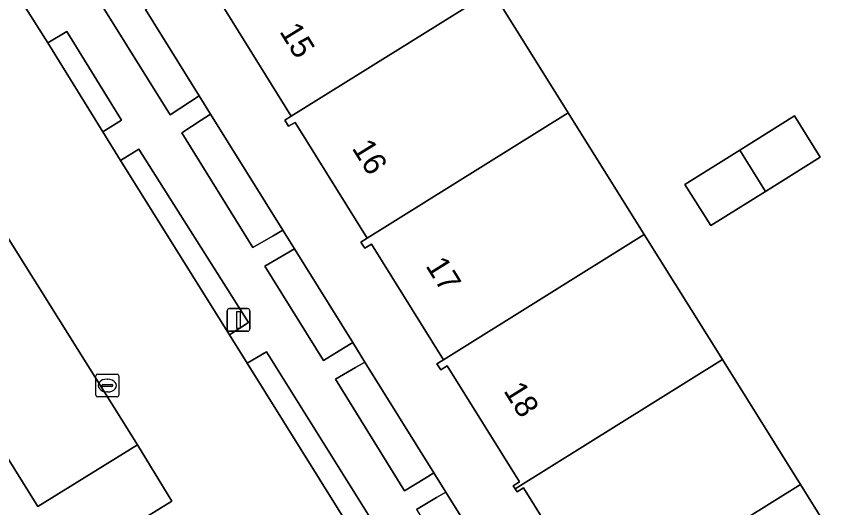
# Model space of a CAD drawing. Extents: x 159279 to 160377, y 384531 to 385888.
# Drawn here: x 159510.12 to 159545.75, y 385322.46 to 385344.02 of the extents above; entities that cross this region are included whole.
import ezdxf

# ---------------------------------------------------------------- set-up
doc = ezdxf.new("R2010")
doc.units = 0
for name, color, linetype in [('IMGEO_Erf', 7, 'Continuous'), ('IMGEO_Groenvoorziening', 7, 'Continuous'), ('IMGEO_Kolk', 7, 'Continuous'), ('IMGEO_Lichtmast', 7, 'Continuous'), ('IMGEO_Pand', 7, 'Continuous'), ('IMGEO_Pand_nummerreeks', 7, 'Continuous'), ('IMGEO_Parkeervlak_open', 7, 'Continuous'), ('IMGEO_Rijbaan_lokaal_open', 7, 'Continuous'), ('IMGEO_Terreindeel_gesloten', 7, 'Continuous'), ('IMGEO_Voetpad_open', 7, 'Continuous')]:
    doc.layers.add(name, color=color, linetype=linetype)

msp = doc.modelspace()

# ---------------------------------------------------------------- linework, layer by layer
at = {"layer": 'IMGEO_Erf'}
msp.add_lwpolyline([(159545.911, 385362.141), (159544.219, 385361.084), (159526.589, 385350.077), (159526.643, 385349.992), (159527.598, 385350.585), (159530.751, 385345.531), (159530.995, 385345.14), (159534.332, 385339.79), (159537.665, 385334.447), (159541.091, 385328.956), (159544.511, 385323.473), (159547.84, 385318.137)], dxfattribs=at)
msp.add_lwpolyline([(159540.589, 385334.838), (159539.447, 385336.633), (159541.856, 385338.146), (159544.259, 385339.654), (159545.385, 385337.84), (159542.987, 385336.339)], close=True, dxfattribs=at)
at = {"layer": 'IMGEO_Groenvoorziening'}
for points in [[(159500.64, 385348.943), (159498.146, 385352.954), (159493.776, 385350.243), (159488.31, 385359.005), (159492.658, 385361.728), (159490.152, 385365.746), (159485.794, 385363.031), (159480.341, 385371.812), (159484.701, 385374.506), (159481.423, 385379.772), (159481.223, 385380.079), (159473.614, 385375.297), (159509.752, 385318.295), (159516.946, 385322.749), (159515.441, 385325.224), (159511.063, 385322.514), (159504.254, 385333.446), (159508.6, 385336.129), (159506.114, 385340.158), (159501.739, 385337.466), (159496.29, 385346.227)], [(159526.567, 385349.945), (159526.643, 385349.992), (159526.589, 385350.077), (159525.637, 385351.642), (159513.967, 385344.361), (159516.864, 385339.703), (159517.725, 385340.259), (159518.148, 385340.532), (159516.872, 385342.583), (159515.793, 385344.318), (159516.58, 385344.813), (159519.338, 385346.547), (159519.862, 385345.731)], [(159511.503, 385342.85), (159513.916, 385338.953), (159514.742, 385339.457), (159512.339, 385343.356)], [(159518.645, 385339.732), (159518.225, 385339.457), (159517.377, 385338.902), (159520.499, 385333.876), (159521.386, 385334.392), (159521.813, 385334.64)], [(159514.691, 385337.689), (159519.469, 385330.043), (159520.3, 385330.582), (159515.497, 385338.189)], [(159522.321, 385333.823), (159521.898, 385333.572), (159521.021, 385333.05), (159523.596, 385328.915), (159524.466, 385329.457), (159524.878, 385329.713)], [(159520.255, 385328.8), (159525.749, 385319.979), (159526.576, 385320.524), (159521.094, 385329.298)], [(159525.415, 385328.849), (159524.997, 385328.606), (159524.117, 385328.095), (159527.153, 385323.192), (159528.035, 385323.738), (159528.439, 385323.988)], [(159528.965, 385323.142), (159528.556, 385322.903), (159527.669, 385322.385), (159530.249, 385318.277), (159531.106, 385318.817), (159531.501, 385319.066)]]:
    msp.add_lwpolyline(points, close=True, dxfattribs=at)
at = {"layer": 'IMGEO_Kolk'}
for p, q in [((159513.689, 385328.32), (159514.541, 385328.32)), ((159513.614, 385327.394), (159513.614, 385328.246)), ((159514.102, 385328.1), (159514.127, 385328.1)), ((159514.615, 385328.246), (159514.615, 385327.394)), ((159513.873, 385327.814), (159513.873, 385327.826)), ((159514.311, 385327.777), (159513.913, 385327.777)), ((159513.916, 385327.863), (159514.314, 385327.863)), ((159514.357, 385327.826), (159514.357, 385327.814)), ((159514.541, 385327.32), (159513.689, 385327.32)), ((159514.125, 385327.54), (159514.1, 385327.54))]:
    msp.add_line(p, q, dxfattribs=at)
for points in [[(159513.689, 385328.32), (159514.541, 385328.32)], [(159513.614, 385327.394), (159513.614, 385328.246)], [(159514.615, 385328.246), (159514.615, 385327.394)], [(159514.541, 385327.32), (159513.689, 385327.32)]]:
    msp.add_lwpolyline(points, dxfattribs=at)
for centre, radius, start, end in [((159513.691, 385328.244), 0.0765, 91.552, 178.448), ((159513.691, 385328.244), 0.0765, 91.552, 178.448), ((159514.539, 385328.244), 0.0765, 1.552, 88.448), ((159514.539, 385328.244), 0.0765, 1.552, 88.448), ((159513.913, 385327.823), 0.0403, 85.8775, 175.7526), ((159513.91, 385327.813), 0.0366, 178.938, 274.7102), ((159514.314, 385327.82), 0.043, 264.8664, 352.4533), ((159514.318, 385327.825), 0.0386, 1.7309, 96.639), ((159513.691, 385327.396), 0.0765, 181.552, 268.448), ((159513.691, 385327.396), 0.0765, 181.552, 268.448), ((159514.539, 385327.396), 0.0765, 271.552, 358.448), ((159514.539, 385327.396), 0.0765, 271.552, 358.448)]:
    msp.add_arc(centre, radius, start, end, dxfattribs=at)
for centre, major_axis, ratio, start_param, end_param in [((159514.101, 385327.82), (-0.387, 0.002), 0.722429, 4.712389, 7.853982), ((159514.126, 385327.82), (-0.39, 0.002), 0.717154, 1.570796, 4.712389)]:
    msp.add_ellipse(centre, major_axis=major_axis, ratio=ratio, start_param=start_param, end_param=end_param, dxfattribs=at)
at = {"layer": 'IMGEO_Lichtmast'}
for p, q in [((159519.472, 385331.198), (159520.262, 385331.198)), ((159520.262, 385331.198), (159519.472, 385331.198)), ((159519.372, 385330.298), (159519.372, 385331.098)), ((159519.372, 385331.098), (159519.372, 385330.298)), ((159520.362, 385331.098), (159520.362, 385330.298)), ((159520.362, 385330.298), (159520.362, 385331.098)), ((159520.262, 385330.198), (159519.472, 385330.198)), ((159519.472, 385330.198), (159520.262, 385330.198))]:
    msp.add_line(p, q, dxfattribs=at)
msp.add_lwpolyline([(159519.792, 385331.073), (159519.942, 385331.073), (159519.942, 385330.323), (159519.792, 385330.323), (159519.792, 385331.073)], dxfattribs=at)
for centre, start, end in [((159519.472, 385331.098), 90, 180), ((159519.472, 385331.098), 90, 180), ((159520.262, 385331.098), 0, 90), ((159520.262, 385331.098), 360, 90), ((159519.472, 385330.298), 180, 270), ((159519.472, 385330.298), 180, 270), ((159520.262, 385330.298), 270, 0), ((159520.262, 385330.298), 270, 0)]:
    msp.add_arc(centre, 0.1, start, end, dxfattribs=at)
at = {"layer": 'IMGEO_Pand'}
for points in [[(159527.598, 385350.585), (159526.643, 385349.992), (159526.567, 385349.945), (159519.862, 385345.731), (159518.525, 385344.89), (159518.698, 385344.614), (159518.995, 385344.793), (159522.171, 385339.635), (159530.995, 385345.14), (159530.751, 385345.531)], [(159534.332, 385339.79), (159530.995, 385345.14), (159522.171, 385339.635), (159521.895, 385339.464), (159522.061, 385339.196), (159522.355, 385339.363), (159525.505, 385334.283)], [(159537.665, 385334.447), (159534.332, 385339.79), (159525.505, 385334.283), (159525.23, 385334.113), (159525.413, 385333.844), (159525.695, 385334.022), (159528.852, 385328.949)], [(159541.856, 385338.146), (159542.987, 385336.339), (159545.385, 385337.84), (159544.259, 385339.654)], [(159542.987, 385336.339), (159541.856, 385338.146), (159539.447, 385336.633), (159540.589, 385334.838)], [(159541.091, 385328.956), (159537.665, 385334.447), (159528.852, 385328.949), (159528.57, 385328.77), (159528.748, 385328.501), (159529.026, 385328.677), (159532.188, 385323.601), (159531.909, 385323.415), (159531.997, 385323.284)], [(159544.511, 385323.473), (159541.091, 385328.956), (159531.997, 385323.284), (159532.084, 385323.155), (159532.372, 385323.337), (159535.532, 385318.259), (159535.244, 385318.069), (159535.419, 385317.802), (159535.707, 385317.981)], [(159547.84, 385318.137), (159544.511, 385323.473), (159535.707, 385317.981), (159538.867, 385312.913), (159538.572, 385312.73), (159538.749, 385312.469), (159539.017, 385312.633)]]:
    msp.add_lwpolyline(points, close=True, dxfattribs=at)
at = {"layer": 'IMGEO_Parkeervlak_open'}
msp.add_lwpolyline([(159508.6, 385336.129), (159504.254, 385333.446), (159511.063, 385322.514), (159515.441, 385325.224)], close=True, dxfattribs=at)
at = {"layer": 'IMGEO_Rijbaan_lokaal_open'}
for points in [[(159520.255, 385328.8), (159519.469, 385330.043), (159514.691, 385337.689), (159513.916, 385338.953), (159511.503, 385342.85), (159510.367, 385344.653), (159503.017, 385356.459)], [(159508.6, 385336.129), (159515.441, 385325.224), (159516.946, 385322.749), (159509.752, 385318.295)], [(159548.124, 385284.071), (159547.47, 385285.17), (159546.236, 385287.125), (159544.248, 385290.361), (159542.263, 385293.526), (159540.128, 385296.932), (159539.25, 385298.267), (159536.35, 385302.972), (159535.574, 385304.213), (159532.61, 385308.995), (159531.825, 385310.237), (159526.527, 385318.725), (159525.749, 385319.979), (159520.255, 385328.8)]]:
    msp.add_lwpolyline(points, dxfattribs=at)
at = {"layer": 'IMGEO_Terreindeel_gesloten'}
for points in [[(159535.532, 385318.259), (159532.372, 385323.337), (159532.084, 385323.155), (159531.997, 385323.284), (159531.909, 385323.415), (159532.188, 385323.601), (159529.026, 385328.677), (159528.748, 385328.501), (159528.57, 385328.77), (159528.852, 385328.949), (159525.695, 385334.022), (159525.413, 385333.844), (159525.23, 385334.113), (159525.505, 385334.283), (159522.355, 385339.363), (159522.061, 385339.196), (159521.895, 385339.464), (159522.171, 385339.635), (159518.995, 385344.793)], [(159515.793, 385344.318), (159516.872, 385342.583), (159518.148, 385340.532), (159518.645, 385339.732), (159521.813, 385334.64), (159522.321, 385333.823), (159524.878, 385329.713), (159525.415, 385328.849), (159528.439, 385323.988), (159528.965, 385323.142), (159531.501, 385319.066)]]:
    msp.add_lwpolyline(points, dxfattribs=at)
at = {"layer": 'IMGEO_Voetpad_open'}
for points in [[(159503.848, 385356.959), (159511.207, 385345.192), (159510.367, 385344.653), (159511.503, 385342.85), (159512.339, 385343.356), (159514.742, 385339.457), (159513.916, 385338.953), (159514.691, 385337.689), (159515.497, 385338.189), (159520.3, 385330.582), (159519.469, 385330.043), (159520.255, 385328.8), (159521.094, 385329.298), (159526.576, 385320.524)], [(159527.669, 385322.385), (159528.556, 385322.903), (159528.965, 385323.142), (159528.439, 385323.988), (159528.035, 385323.738), (159527.153, 385323.192), (159524.117, 385328.095), (159524.997, 385328.606), (159525.415, 385328.849), (159524.878, 385329.713), (159524.466, 385329.457), (159523.596, 385328.915), (159521.021, 385333.05), (159521.898, 385333.572), (159522.321, 385333.823), (159521.813, 385334.64), (159521.386, 385334.392), (159520.499, 385333.876), (159517.377, 385338.902), (159518.225, 385339.457), (159518.645, 385339.732), (159518.148, 385340.532), (159517.725, 385340.259), (159516.864, 385339.703), (159513.967, 385344.361)]]:
    msp.add_lwpolyline(points, dxfattribs=at)

# ---------------------------------------------------------------- texts
at = {"layer": 'IMGEO_Pand_nummerreeks'}
for s, rotation, p in [('15', 301.6213, (159521.641, 385343.355)), ('16', 301.8047, (159524.818, 385338.238)), ('17', 301.8963, (159528.05, 385333.076)), ('18', 301.9193, (159531.469, 385327.592))]:
    msp.add_text(s, height=1, rotation=rotation, dxfattribs=at).set_placement(p)

doc.saveas('drawing.dxf')
